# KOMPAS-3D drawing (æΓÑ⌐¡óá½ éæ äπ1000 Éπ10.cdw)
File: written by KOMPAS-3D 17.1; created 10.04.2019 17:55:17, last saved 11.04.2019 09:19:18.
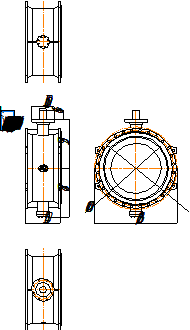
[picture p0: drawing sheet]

Sheet 1: A4, portrait

Title block, sheet 1: name: Стейнвал ВС Ду1000 Ру10; material: Внимание! Данный продукт является объектом авторского права ООО «Торговый Дом АДЛ». / Запрещается изменение, копирование, распространение / (в том числе путем копирования на другие сайты и ресурсы в Интернете) / или любое иное использование информации и объектов без предварительного / согласия правообладателя (ООО «Торговый Дом АДЛ»).; mass: 1025,55; sheets: 1; organisation: ООО "Торговый дом АДЛ"; sheet format: A4; stored path: \\adlc.lan\data\АДЛ_ПКД\3D-модели\ADL production\Дисковые поворотные затворы СТЕЙНВАЛ\Двухэксцентриковый ВС\KOMPAS 2D\Стейнвал ВС Ду1000 Ру10.cdw

Views: Вид 1, Проекционный вид 2, Проекционный вид 3
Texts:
  user
Dimensions and other numbers on the sheet: 100; 350; 540; 739; 748; 146; 1:1; 1; 1025,55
